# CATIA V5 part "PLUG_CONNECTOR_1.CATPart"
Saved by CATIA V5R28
Part number: PLUG_CONNECTOR_1
Revision: ---
Publications: "MasterKeywayAxis", "InsertFrontFace", "InsertRearFace", "Logical Termination.1", "Logical Pin.1", "CCP", "Face_generated(CCP)", "Axis_generated(CCP)", "Face_generated(CCP).1", "BCP", "BCPRPoint_generated(BCP)", "BCPPlane_generated(BCP)", "BaCP", "Face_generated(BaCP)", "Axis_generated(BaCP)", "Face_generated(BaCP).1", "CaCP", "CaCPRPoint_generated(CaCP)", "Face_generated(CaCP)", "Axis_generated(CaCP)", "Face_generated(CaCP).1"
Bounding box of the stored display mesh (mm): x 0 to 33.16, y -12.5 to 12.5, z -12.49 to 12.49
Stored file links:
  C:\Users\ajc8720\Documents\BOEING_WORK\0001-2CES\004-AP242\Boeing-Generic_Harness_R3\PLUG_CONNECTOR_1.CATPart
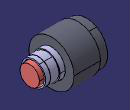
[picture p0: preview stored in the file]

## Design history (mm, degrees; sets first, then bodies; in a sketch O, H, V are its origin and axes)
Parameters
  PartNumber = "PLUG_CONNECTOR_1"
AxisSystem1 "MasterKeywayAxis": origin (0, 0, 0), X (1, 0, 0), Y (0, 1, 0), Z (0, 0, 1)
Set1 "EGF"
  Set2 "CCP"
    Point1 "CCPRPoint": (15.01 {= deleted_ShoulderFront}, 0, 0)
  Set3 "BaCP"
    Point2 "BaCPRPoint": (31 {= deleted_ShellLength}, 0, 0)
  Set4 "BCP"
    Plane1 "BCPPlane": type Offset, RefPlane face of Pad6, Offset 0, reversed
    Point3 "BCPRPoint": type OnPlane, Support Plane1, H 0, V 0, Direction (0, 1, 0)
  Set5 "CaCP"
    Point4 "CaCPRPoint": (15.01 {= deleted_ShoulderFront}, 0, 0)
    Plane2 "CaCPPlane": type OffsetPt, RefPlane yz-plane, RefPoint Point4
Body1 "CouplingRing" (main body)
  Sketch1 on yz-plane, origin (0, 0, 0), H (0, 1, 0), V (0, 0, 1)
    circle A1 centre (0, 0) radius 12.5
    radius A1 = 12.5
  Pad1 "CouplingRing": profile Sketch1, direction (1, 0, 0), length 21.06 {= deleted_CouplingRingFront + deleted_CouplingRingLength}, opposite side length -1.68 {= -( deleted_CouplingRingFront )}
  Sketch2 on zx-plane, origin (0, 0, 0), H (-1, 0, 0), V (0, 0, 1)
    line L1 (-6.38, 12.5) -> (-1.68, 12.5)
    line L2 (-1.68, 12.5) -> (-1.68, 11.8)
    line L3 (-1.68, 11.8) -> (-6.38, 11.8)
    line L4 (-6.38, 11.8) -> (-6.38, 12.5)
    distance L2 V = 1.68
    distance L4 L2 = 4.7
    distance L1 H = 12.5
    distance L3 L1 = 0.7
    horizontal: L1 H, L3 H
    vertical: L2 V, L4 V
  Groove1 "CouplingRingRelief": profile Sketch2, axis Sketch2.H, angle 360
  Sketch3 on face of Pad1, origin (1.68, 0, 0), H (0, -1, 0), V (0, 0, 1)
    point P1 (0, 0)
    reference intersected line E1 through (0, 0) direction (-1, 0) from xy-plane
    reference intersected line E2 through (0, 0) direction (0, -1) from zx-plane
    coincidence: P1 E1, P1 E2
  Hole1 "CouplingRingID": placed by Sketch3, at (1.68, 0, 0) direction (1, 0, 0), diameter 19.35 {= deleted_CouplingRingThreadDia}, depth 18.36 {= deleted_CouplingRingThreadLength}, counterbore diameter 19.69 {= deleted_CouplingRingFrontID}, counterbore depth 2.14 {= deleted_CouplingRingFrontIDLength}
  Sketch4 on face of Hole1, origin (20.04, 0, 0), H (0, 1, 0), V (0, 0, -1)
    point P1 (0, 0)
    reference intersected line E1 through (0, 0) direction (0, 1) from zx-plane
    reference intersected line E2 through (0, 0) direction (1, 0) from xy-plane
    coincidence: P1 E1, P1 E2
  Hole2 "CouplingRingThruHole": placed by Sketch4, at (20.04, 0, 0) direction (1, 0, 0), diameter 15.4 {= deleted_CouplingRingThruDia}, through (limit type 6)
Body2 "Shell"
  Sketch5 on yz-plane, origin (0, 0, 0), H (0, 1, 0), V (0, 0, 1)
    circle A1 centre (0, 0) radius 7.15
    radius A1 = 7.15 {= deleted_ShellFrontOD / 2}
  Pad2 "ShellFront": profile Sketch5, direction (1, 0, 0), length 15.01 {= deleted_ShoulderFront}
  Sketch6 on yz-plane, origin (0, 0, 0), H (0, 1, 0), V (0, 0, 1)
    circle A1 centre (0, 0) radius 7.5
    radius A1 = 7.5 {= deleted_ShoulderOD / 2}
  Pad3 "ShellBack": profile Sketch6, direction (1, 0, 0), length 31 {= deleted_ShellLength}, opposite side length -15.01 {= -( deleted_ShoulderFront )}
  Sketch7 on zx-plane, origin (0, 0, 0), H (-1, 0, 0), V (0, 0, 1)
    line L1 (-31, 7.5) -> (-23.89, 7.5)
    line L2 (-28.46, 6.96) -> (-28.46, 6.78)
    line L3 (-28.46, 6.78) -> (-31, 6.78)
    line L4 (-31, 6.78) -> (-31, 7.5)
    line L5 (-23.89, 7.5) -> (-23.89, 6.96)
    line L6 (-23.89, 6.96) -> (-28.46, 6.96)
    distance V L4 = 31 {= deleted_ShellLength}
    length L1 = 7.11 {= deleted_AccThreadLength}
    length L3 = 2.54 {= deleted_ShellRearODLength}
    distance H L3 = 6.78 {= deleted_ShellRearOD / 2}
    distance H L6 = 6.96 {= deleted_AccThreadDia / 2}
    distance L1 H = 7.5 {= deleted_ShoulderOD / 2}
    horizontal: L1 H, L3 H, L6 H
    vertical: L2 V, L4 V, L5 V
  Groove2 "AccyTeethThread": profile Sketch7, axis Sketch7.H, angle 360
  Sketch8 on yz-plane, origin (0, 0, 0), H (0, 1, 0), V (0, 0, 1)
    point P1 (-1.27, 0)
    line L1 (-1.27, 0) -> (1.27, 0)
    line L2 (1.27, 0) -> (1.27, 7.69)
    line L3 (1.27, 7.69) -> (-1.27, 7.69)
    line L4 (-1.27, 7.69) -> (-1.27, 0)
    length L3 = 2.54 {= deleted_MasterKeyWidth}
    distance H L3 = 7.69 {= deleted_MasterKeyDia / 2}
    coincidence: P1 H
    horizontal: L1 H, L3 H
    vertical: L2 V, L4 V
    symmetry: L2 L4 V
  Pad4 "MasterKeyway": profile Sketch8, direction (1, 0, 0), length 15.01 {= deleted_ShoulderFront}, opposite side length -0.76 {= - ( deleted_MasterKeyFront )}
  Sketch9 on face of Pad2, origin (0, 0, 0), H (0, -1, 0), V (0, 0, 1)
    point P1 (0, 0)
    reference intersected line E1 through (0, 0) direction (0, -1) from zx-plane
    reference intersected line E2 through (0, 0) direction (-1, 0) from xy-plane
    coincidence: P1 E1, P1 E2
  Hole3 "FrontShellID": placed by Sketch9, at (0, 0, 0) direction (1, 0, 0), diameter 10.92 {= deleted_ShellFrontID}, depth 20.46 {= deleted_ShellLength - deleted_ShellRearIDLength}
  Sketch10 on face of Pad3, origin (31, 0, 0), H (0, 1, 0), V (0, 0, 1)
    point P1 (0, 0)
    reference intersected line E1 through (0, 0) direction (0, 1) from zx-plane
    reference intersected line E2 through (0, 0) direction (-1, 0) from xy-plane
    coincidence: P1 E1, P1 E2
  Hole4 "RearShellID": placed by Sketch10, at (31, 0, 0) direction (-1, 0, 0), diameter 12.07 {= deleted_ShellRearID}, depth 10.54 {= deleted_ShellRearIDLength}
Body3 "Insert"
  Sketch11 on yz-plane, origin (0, 0, 0), H (0, 1, 0), V (0, 0, 1)
    circle A1 centre (0, 0) radius 5.245
    radius A1 = 5.245 {= deleted_InsertFrontOD / 2}
  Pad5 "InsertOD": profile Sketch11, direction (1, 0, 0), length 20.46 {= deleted_InsertFront + deleted_InsertLength - deleted_GrommetLength}, opposite side length -14.57 {= -( deleted_InsertFront )}
  Sketch12 on yz-plane, origin (0, 0, 0), H (0, 1, 0), V (0, 0, 1)
    circle A1 centre (0, 0) radius 5.425
    radius A1 = 5.425 {= deleted_GrommetOD / 2}
  Pad6 "GrommetOD": profile Sketch12, direction (1, 0, 0), length 33.16 {= deleted_InsertFront + deleted_InsertLength}, opposite side length -20.46 {= -( deleted_InsertFront + deleted_InsertLength - deleted_GrommetLength )}
Body4 "CaCP"
  Sketch13 "Sketch" on Plane2, origin (15.01, 0, 0), H (0, 1, 0), V (0, 0, 1)
    line L1 (-0.672, 0.762) -> (0.672, 0.762)
    point P1 (-0.672, 0.762)
    point P2 (0.672, 0.762)
    arc A1 centre (0, 0) radius 1.016 from (-1.016, 0) to (1.016, 0) ccw
    point P3 (0, 0)
    point P4 (-1.016, 0)
    point P5 (1.016, 0)
    reference projected point E1 (0, 0) from Point4
    arc A2 centre (0, 0) radius 1.016 from (1.016, 0) to (0.672, 0.762) ccw
    point P6 (0, 0)
    point P7 (1.016, 0)
    point P8 (0.672, 0.762)
    arc A3 centre (0, 0) radius 1.016 from (-0.672, 0.762) to (-1.016, 0) ccw
    point P9 (0, 0)
    point P10 (-0.672, 0.762)
    point P11 (-1.016, 0)
    reference projected point E2 (0, 0) from Point4
    reference projected point E3 (0, 0) from Point4
    length L1 = 1.344
    radius A1 = 1.016
    radius A3 = 1.016
    radius A2 = 1.016
    distance L1 P5 = 0.762
    distance P4 L1 = 0.762
    distance P7 L1 = 0.762
    distance P11 L1 = 0.762
    coincidence: P3 E1, P6 E2, P9 E3, P8 P2, P10 P1
    horizontal: L1 H
  Pad7: profile Sketch13, direction (1, 0, 0), length 0.508, opposite side up to Plane2
Body5 "CCP"
  Sketch14 on face of Pad3, origin (15.01, 0, 0), H (0, 1, 0), V (0, 0, 1)
    arc A1 centre (0, 0) radius 1.016 from (-0.672, 0.762) to (0.672, 0.762) ccw
    line L1 (-0.672, 0.762) -> (0.672, 0.762)
    distance L1 H = 0.762
    radius A1 = 1.016
  Pad8: profile Sketch14, direction (1, 0, 0), length 0.508
Body6 "BaCP"
  Sketch15 on face of Pad3, origin (31, 0, 0), H (0, 1, 0), V (0, 0, 1)
    arc A1 centre (0, 0) radius 1.016 from (-0.672, 0.762) to (0.672, 0.762) ccw
    line L1 (-0.672, 0.762) -> (0.672, 0.762)
    distance L1 H = 0.762
    radius A1 = 1.016
  Sketch16 on face of Pad3, origin (31, 0, 0), H (0, 1, 0), V (0, 0, 1)
    circle A1 centre (0, 0) radius 1.27
    radius A1 = 1.27
  Pad9: profile Sketch16, direction (1, 0, 0), length 0.254, opposite side length 0.254
  Pocket1: profile Sketch15, direction (1, 0, 0), through (limit type 6)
